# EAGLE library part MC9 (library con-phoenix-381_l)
Mini-Combicon 3.81mm horizontal 9-polig (ohne Gegenstecker)
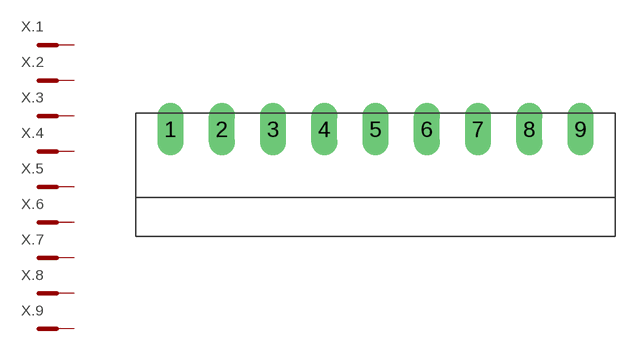
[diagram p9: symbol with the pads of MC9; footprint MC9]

Designator prefix X; gates .1=MCST .2=MCST .3=MCST .4=MCST .5=MCST .6=MCST .7=MCST .8=MCST .9=MCST

## MC9  [MC9]
1  .1:SK  pas
2  .2:SK  pas
3  .3:SK  pas
4  .4:SK  pas
5  .5:SK  pas
6  .6:SK  pas
7  .7:SK  pas
8  .8:SK  pas
9  .9:SK  pas

## Footprint MC9 (pad centres in mm)
Mini-Combicon 3.81mm horizontal 9-polig (ohne Gegenstecker)
drill 1.3 long: 1 -15.24,0; 2 -11.43,0; 3 -7.62,0; 4 -3.81,0; 5 0,0; 6 3.81,0; 7 7.62,0; 8 11.43,0; 9 15.24,0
